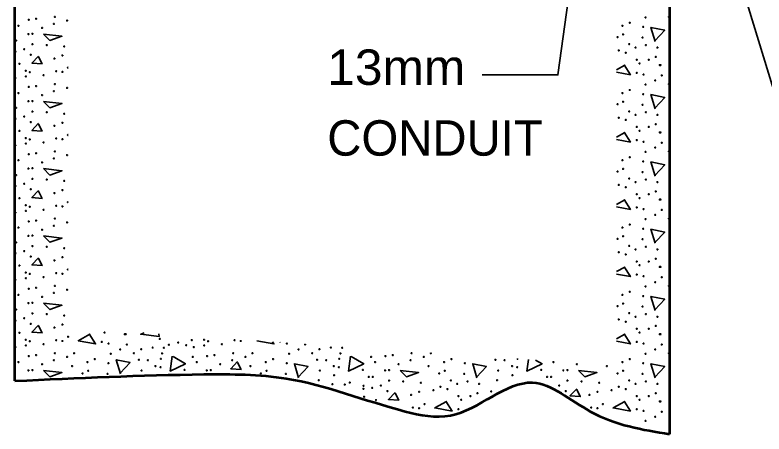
# Model space of a CAD drawing. Extents: x -31 to 824, y -13 to 531.
# Drawn here: x 505.9 to 556.7, y 172.6 to 201 of the extents above; entities that cross this region are included whole.
import ezdxf

# ---------------------------------------------------------------- set-up
doc = ezdxf.new("R2010")
doc.units = 0
doc.header["$LTSCALE"] = 1.2
doc.layers.add('1', color=7, linetype='Continuous', lineweight=35)

msp = doc.modelspace()

# ---------------------------------------------------------------- linework, layer by layer
at = {"layer": '1'}
for p, q in [((547.226, 197.638), (546.658, 197.328)), ((547.226, 193.078), (546.658, 192.768)), ((547.226, 188.518), (546.658, 188.208)), ((547.226, 183.958), (546.658, 183.648)), ((547.226, 179.398), (546.658, 179.088)), ((522.255, 178.964), (522.255, 178.964))]:
    msp.add_line(p, q, dxfattribs=at)
at = {"layer": '1', "lineweight": 53}
msp.add_lwpolyline([(505.858, 176.24), (505.858, 249.44), (550.258, 249.44), (550.258, 172.64)], dxfattribs=at)
at = {"layer": '1'}
for points in [[(544.964, 213.44), (542.694, 196.977), (537.542, 196.977)], [(552.058, 213.14), (563.156, 176.937), (582.616, 176.937)], [(549.29, 199.246), (549.002, 200.206), (549.938, 200.014), (549.266, 199.294)], [(507.458, 198.262), (507.002, 197.782), (507.698, 197.734), (507.458, 198.214)], [(546.658, 197.165), (547.61, 196.99), (547.178, 197.662)], [(549.29, 194.686), (549.002, 195.646), (549.938, 195.454), (549.266, 194.734)], [(507.458, 193.702), (507.002, 193.222), (507.698, 193.174), (507.458, 193.654)], [(546.658, 192.605), (547.61, 192.43), (547.178, 193.102)], [(549.29, 190.126), (549.002, 191.086), (549.938, 190.894), (549.266, 190.174)], [(507.458, 189.142), (507.002, 188.662), (507.698, 188.614), (507.458, 189.094)], [(546.658, 188.045), (547.61, 187.87), (547.178, 188.542)], [(549.29, 185.566), (549.002, 186.526), (549.938, 186.334), (549.266, 185.614)], [(507.458, 184.582), (507.002, 184.102), (507.698, 184.054), (507.458, 184.534)], [(546.658, 183.485), (547.61, 183.31), (547.178, 183.982)], [(549.29, 181.006), (549.002, 181.966), (549.938, 181.774), (549.266, 181.054)], [(507.458, 180.022), (507.002, 179.542), (507.698, 179.494), (507.458, 179.974)], [(510.938, 179.398), (510.146, 178.966), (511.322, 178.75), (510.89, 179.422)], [(514.625, 179.491), (514.394, 179.398), (515.642, 179.254), (515.605, 179.424)], [(546.658, 178.925), (547.61, 178.75), (547.178, 179.422)], [(522.255, 178.964), (523.418, 178.75), (523.328, 178.889)], [(516.578, 177.886), (517.418, 177.406), (516.386, 176.902), (516.53, 177.91)], [(528.674, 177.886), (529.514, 177.406), (528.482, 176.902), (528.626, 177.91)], [(513.017, 176.715), (512.729, 177.674), (513.665, 177.483), (512.993, 176.763)], [(520.951, 177.545), (520.495, 177.065), (521.191, 177.017), (520.951, 177.497)], [(525.098, 176.446), (524.81, 177.406), (525.746, 177.214), (525.074, 176.494)], [(537.194, 176.446), (536.906, 177.406), (537.842, 177.214), (537.17, 176.494)], [(541.174, 177.655), (541.61, 177.406), (540.578, 176.902), (540.69, 177.689)], [(549.29, 176.446), (549.002, 177.406), (549.938, 177.214), (549.266, 176.494)], [(531.65, 175.462), (531.194, 174.982), (531.89, 174.934), (531.65, 175.414)], [(543.963, 175.708), (543.507, 175.228), (544.203, 175.18), (543.963, 175.66)], [(535.13, 174.838), (534.338, 174.406), (535.514, 174.19), (535.082, 174.862)], [(547.226, 174.838), (546.434, 174.406), (547.61, 174.19), (547.178, 174.862)]]:
    msp.add_lwpolyline(points, dxfattribs=at)
for points in [[(507.794, 199.75), (509.042, 199.606), (508.226, 199.318)], [(507.794, 195.19), (509.042, 195.046), (508.226, 194.758)], [(507.794, 190.63), (509.042, 190.486), (508.226, 190.198)], [(507.794, 186.07), (509.042, 185.926), (508.226, 185.638)], [(507.794, 181.51), (509.042, 181.366), (508.226, 181.078)], [(507.794, 176.95), (509.042, 176.806), (508.226, 176.518)], [(531.986, 176.95), (533.234, 176.806), (532.418, 176.518)], [(544.082, 176.95), (545.33, 176.806), (544.514, 176.518)]]:
    msp.add_lwpolyline(points, close=True, dxfattribs=at)
for centre in [(506.792, 200.727), (507.294, 200.791), (508.567, 200.918), (548.64, 200.886), (550.214, 200.918), (506.092, 200.313), (507.692, 200.17), (508.503, 200.441), (509.394, 200.663), (547.065, 200.313), (547.558, 200.52), (548.481, 200.234), (506.768, 199.754), (507.04, 199.773), (547.113, 199.725), (505.933, 199.311), (546.731, 199.55), (548.433, 199.518), (506.49, 198.723), (507.04, 199.057), (508.01, 199.009), (509.203, 198.913), (546.811, 198.643), (547.526, 199.073), (547.956, 198.834), (548.656, 199.009), (549.435, 198.834), (505.901, 198.569), (506.929, 198.347), (509.076, 198.299), (547.288, 198.49), (549.324, 198.203), (506.156, 197.742), (508.535, 198.092), (548.035, 198.013), (548.226, 197.758), (548.846, 198.013), (549.594, 197.647), (549.658, 197.647), (506.585, 197.265), (506.865, 197.169), (508.662, 197.233), (509.076, 197.185), (548.035, 197.122), (506.601, 196.883), (507.803, 196.962), (548.497, 197.01), (549.292, 196.613), (549.737, 196.947), (506.792, 196.167), (507.294, 196.231), (508.567, 196.358), (509.394, 196.103), (548.64, 196.326), (550.214, 196.358), (506.092, 195.753), (507.692, 195.61), (508.503, 195.881), (547.065, 195.753), (547.558, 195.96), (548.481, 195.674), (506.768, 195.194), (507.04, 195.213), (547.113, 195.165), (505.933, 194.751), (546.731, 194.99), (548.433, 194.958), (506.49, 194.163), (507.04, 194.497), (508.01, 194.449), (509.203, 194.353), (546.811, 194.083), (547.526, 194.513), (547.956, 194.274), (548.656, 194.449), (549.435, 194.274), (505.901, 194.009), (506.929, 193.787), (509.076, 193.739), (547.288, 193.93), (549.324, 193.643), (506.156, 193.182), (508.535, 193.532), (548.035, 193.453), (548.226, 193.198), (548.846, 193.453), (549.594, 193.087), (549.658, 193.087), (506.585, 192.705), (506.865, 192.609), (508.662, 192.673), (509.076, 192.625), (548.035, 192.562), (506.601, 192.323), (507.803, 192.402), (548.497, 192.45), (549.292, 192.053), (549.737, 192.387), (506.792, 191.607), (507.294, 191.671), (508.567, 191.798), (509.394, 191.543), (548.64, 191.766), (550.214, 191.798), (506.092, 191.193), (507.692, 191.05), (508.503, 191.321), (547.065, 191.193), (547.558, 191.4), (548.481, 191.114), (506.768, 190.634), (507.04, 190.653), (547.113, 190.605), (505.933, 190.191), (546.731, 190.43), (548.433, 190.398), (506.49, 189.603), (507.04, 189.937), (508.01, 189.889), (509.203, 189.793), (546.811, 189.523), (547.526, 189.953), (547.956, 189.714), (548.656, 189.889), (549.435, 189.714), (505.901, 189.449), (506.929, 189.227), (509.076, 189.179), (547.288, 189.37), (549.324, 189.083), (506.156, 188.622), (508.535, 188.972), (548.035, 188.893), (548.226, 188.638), (548.846, 188.893), (549.594, 188.527), (549.658, 188.527), (506.585, 188.145), (506.865, 188.049), (508.662, 188.113), (509.076, 188.065), (548.035, 188.002), (506.601, 187.763), (507.803, 187.842), (548.497, 187.89), (549.292, 187.493), (549.737, 187.827), (506.792, 187.047), (507.294, 187.111), (508.567, 187.238), (509.394, 186.983), (548.64, 187.206), (550.214, 187.238), (506.092, 186.633), (507.692, 186.49), (508.503, 186.761), (547.065, 186.633), (547.558, 186.84), (548.481, 186.554), (506.768, 186.074), (507.04, 186.093), (547.113, 186.045), (505.933, 185.631), (546.731, 185.87), (548.433, 185.838), (506.49, 185.043), (507.04, 185.377), (508.01, 185.329), (509.203, 185.233), (546.811, 184.963), (547.526, 185.393), (547.956, 185.154), (548.656, 185.329), (549.435, 185.154), (505.901, 184.889), (506.929, 184.667), (509.076, 184.619), (547.288, 184.81), (549.324, 184.523), (506.156, 184.062), (508.535, 184.412), (548.035, 184.333), (548.226, 184.078), (548.846, 184.333), (549.594, 183.967), (549.658, 183.967), (506.585, 183.585), (506.865, 183.489), (508.662, 183.553), (509.076, 183.505), (548.035, 183.442), (506.601, 183.203), (507.803, 183.282), (548.497, 183.33), (549.292, 182.933), (549.737, 183.267), (506.792, 182.487), (507.294, 182.551), (508.567, 182.678), (509.394, 182.423), (548.64, 182.646), (550.214, 182.678), (506.092, 182.073), (507.692, 181.93), (508.503, 182.201), (547.065, 182.073), (547.558, 182.28), (548.481, 181.994), (506.768, 181.514), (507.04, 181.533), (547.113, 181.485), (505.933, 181.071), (546.731, 181.31), (548.433, 181.278), (506.49, 180.483), (507.04, 180.817), (508.01, 180.769), (509.203, 180.673), (546.811, 180.403), (547.526, 180.833), (547.956, 180.594), (548.656, 180.769), (549.435, 180.594), (505.901, 180.329), (506.929, 180.107), (508.535, 179.852), (509.076, 180.059), (547.288, 180.25), (549.324, 179.963), (506.156, 179.502), (511.938, 179.518), (513.306, 179.407), (513.37, 179.407), (548.035, 179.773), (548.226, 179.518), (548.846, 179.773), (549.594, 179.407), (549.658, 179.407), (506.585, 179.025), (506.865, 178.929), (508.662, 178.993), (509.076, 178.945), (509.457, 179.232), (511.747, 178.882), (515.676, 179.088), (516.932, 178.834), (517.854, 179.009), (518.681, 179.025), (518.961, 178.929), (520.758, 178.993), (521.172, 178.945), (548.035, 178.882), (506.601, 178.643), (507.803, 178.722), (512.209, 178.77), (513.004, 178.373), (513.449, 178.707), (514.419, 178.388), (515.198, 178.5), (515.962, 178.484), (516.296, 178.691), (517.473, 178.659), (517.982, 178.532), (518.697, 178.643), (519.899, 178.722), (524.305, 178.77), (525.1, 178.373), (526.515, 178.388), (527.294, 178.5), (528.058, 178.484), (548.497, 178.77), (549.292, 178.373), (549.737, 178.707), (506.792, 177.927), (507.294, 177.991), (508.567, 178.118), (509.394, 177.863), (509.871, 178.118), (512.352, 178.086), (513.926, 178.118), (515.835, 178.102), (517.918, 177.863), (518.888, 177.927), (519.39, 177.991), (520.663, 178.118), (521.49, 177.863), (521.967, 178.118), (524.448, 178.086), (526.022, 178.118), (527.931, 178.102), (530.014, 177.863), (530.984, 177.927), (531.486, 177.991), (532.759, 178.118), (533.586, 177.863), (548.64, 178.086), (550.214, 178.118), (506.092, 177.513), (507.692, 177.37), (508.503, 177.641), (510.777, 177.513), (511.27, 177.72), (512.193, 177.434), (514.26, 177.673), (514.88, 177.641), (515.755, 177.736), (518.188, 177.513), (519.788, 177.37), (520.599, 177.641), (522.873, 177.513), (523.366, 177.72), (524.289, 177.434), (526.356, 177.673), (526.976, 177.641), (527.851, 177.736), (530.284, 177.513), (531.884, 177.37), (532.695, 177.641), (534.969, 177.513), (535.462, 177.72), (536.385, 177.434), (538.452, 177.673), (539.072, 177.641), (542.38, 177.513), (543.98, 177.37), (547.065, 177.513), (547.558, 177.72), (548.481, 177.434), (506.768, 176.954), (507.04, 176.973), (509.728, 177.243), (510.825, 176.925), (514.451, 176.941), (515.389, 177.243), (515.739, 177.163), (517.361, 176.988), (518.864, 176.954), (519.136, 176.973), (521.824, 177.243), (522.921, 176.925), (526.547, 176.941), (527.485, 177.243), (527.835, 177.163), (529.457, 176.988), (530.96, 176.954), (531.232, 176.973), (533.92, 177.243), (535.017, 176.925), (538.643, 176.941), (539.581, 177.243), (539.931, 177.163), (541.553, 176.988), (543.056, 176.954), (543.328, 176.973), (546.016, 177.243), (547.113, 176.925), (510.443, 176.75), (512.145, 176.718), (522.539, 176.75), (524.241, 176.718), (526.467, 176.288), (527.501, 176.623), (529.855, 176.511), (530.125, 176.511), (534.635, 176.75), (536.337, 176.718), (538.563, 176.288), (539.597, 176.623), (541.951, 176.511), (542.221, 176.511), (546.731, 176.75), (548.433, 176.718), (527.39, 176.018), (528.233, 175.986), (528.567, 176.129), (529.505, 175.907), (530.682, 175.923), (531.232, 176.257), (532.202, 176.209), (533.395, 176.113), (534.715, 175.843), (535.43, 176.273), (535.86, 176.034), (536.56, 176.209), (537.339, 176.034), (542.778, 175.923), (543.328, 176.257), (544.298, 176.209), (545.491, 176.113), (546.811, 175.843), (547.526, 176.273), (547.956, 176.034), (548.656, 176.209), (549.435, 176.034), (529.489, 175.706), (530.093, 175.769), (531.121, 175.547), (532.727, 175.292), (533.268, 175.499), (534.238, 175.61), (535.192, 175.69), (537.228, 175.403), (538.166, 175.531), (542.189, 175.769), (543.217, 175.547), (544.823, 175.292), (545.364, 175.499), (546.334, 175.61), (547.288, 175.69), (549.324, 175.403), (529.537, 175.165), (530.348, 174.942), (535.939, 175.213), (536.13, 174.958), (536.75, 175.213), (548.035, 175.213), (548.226, 174.958), (548.846, 175.213), (549.594, 174.847), (549.658, 174.847), (532.854, 174.433), (533.268, 174.385), (533.649, 174.672), (535.939, 174.322), (544.95, 174.433), (545.364, 174.385), (545.745, 174.672), (548.035, 174.322), (548.497, 174.21), (549.292, 173.813), (549.737, 174.147), (548.64, 173.526)]:
    msp.add_circle(centre, 0.0318, dxfattribs=at)
for centre, start, end in [((550.262, 198.331), 97.8617, 262.1383), ((509.457, 197.472), 89.4527, 270.5473), ((505.886, 196.772), 207.5518, 152.4482), ((550.262, 193.771), 97.8617, 262.1383), ((509.457, 192.912), 89.4527, 270.5473), ((505.886, 192.212), 207.5518, 152.4482), ((550.262, 189.211), 97.8617, 262.1383), ((509.457, 188.352), 89.4527, 270.5473), ((505.886, 187.652), 207.5518, 152.4482), ((550.262, 184.651), 97.8617, 262.1383), ((509.457, 183.792), 89.4527, 270.5473), ((505.886, 183.092), 207.5518, 152.4482), ((550.262, 180.091), 97.8617, 262.1383), ((505.886, 178.532), 207.5518, 152.4482), ((523.843, 178.882), 236.9252, 295.1612), ((525.545, 178.707), 108.2003, 63.8861), ((534.063, 178.118), 110.8468, 61.2396), ((539.947, 177.736), 169.3639, 2.7224), ((550.262, 175.531), 97.8617, 262.1383)]:
    msp.add_arc(centre, 0.0318, start, end, dxfattribs=at)
at = {"layer": '1', "lineweight": 53}
msp.add_spline([(505.858, 176.24), (518.676, 176.686), (524.249, 176.407), (532.331, 174.177), (535.396, 173.898), (540.969, 176.128), (544.87, 174.177), (550.258, 172.64)], degree=3, dxfattribs=at)

# ---------------------------------------------------------------- texts
at = {"layer": '1', "width": 1.05}
msp.add_text('13mm', height=2.4, dxfattribs=at).set_placement((527.041, 196.308))
at = {"layer": '1'}
msp.add_text('CONDUIT', height=2.4, dxfattribs=at).set_placement((527.041, 191.508))

doc.saveas('drawing.dxf')
